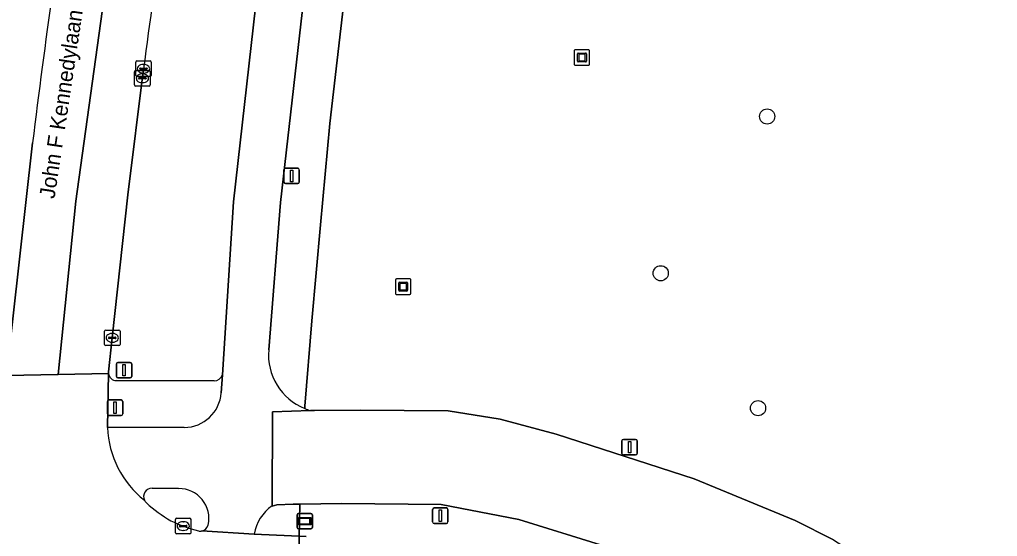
# Model space of a CAD drawing. Extents: x 161477 to 163040, y 383680 to 384871.
# Drawn here: x 161513.6 to 161576.6, y 384158.1 to 384191.4 of the extents above; entities that cross this region are included whole.
import ezdxf

# ---------------------------------------------------------------- set-up
doc = ezdxf.new("R2010")
doc.units = 0
for name, color, linetype in [('IMGEO_Afsluitpaal', 7, 'Continuous'), ('IMGEO_Berm_groen', 7, 'Continuous'), ('IMGEO_Boom', 7, 'Continuous'), ('IMGEO_Fietspad_gesloten', 7, 'Continuous'), ('IMGEO_Groenvoorziening', 7, 'Continuous'), ('IMGEO_Informatiebord', 7, 'Continuous'), ('IMGEO_Kolk', 7, 'Continuous'), ('IMGEO_Kunstobject', 7, 'Continuous'), ('IMGEO_Lichtmast', 7, 'Continuous'), ('IMGEO_Openbare_ruimte_label', 7, 'Continuous'), ('IMGEO_Rijbaan_lokaal_gesloten', 7, 'Continuous'), ('IMGEO_Verkeerseiland_open', 7, 'Continuous'), ('IMGEO_Voetpad_open', 7, 'Continuous')]:
    doc.layers.add(name, color=color, linetype=linetype)

msp = doc.modelspace()

# ---------------------------------------------------------------- linework, layer by layer
at = {"layer": 'IMGEO_Afsluitpaal'}
for p, q in [((161540.238, 384159.033), (161540.238, 384159.833)), ((161540.238, 384159.833), (161540.238, 384159.033)), ((161540.338, 384159.933), (161541.128, 384159.933)), ((161541.128, 384159.933), (161540.338, 384159.933)), ((161541.228, 384159.833), (161541.228, 384159.033)), ((161541.228, 384159.033), (161541.228, 384159.833)), ((161541.128, 384158.933), (161540.338, 384158.933)), ((161540.338, 384158.933), (161541.128, 384158.933))]:
    msp.add_line(p, q, dxfattribs=at)
msp.add_lwpolyline([(161540.658, 384159.808), (161540.808, 384159.808), (161540.808, 384159.058), (161540.658, 384159.058), (161540.658, 384159.808)], dxfattribs=at)
for centre, start, end in [((161540.338, 384159.833), 90, 180), ((161540.338, 384159.833), 90, 180), ((161541.128, 384159.833), 0, 90), ((161541.128, 384159.833), 360, 90), ((161540.338, 384159.033), 180, 270), ((161540.338, 384159.033), 180, 270), ((161541.128, 384159.033), 270, 0), ((161541.128, 384159.033), 270, 0)]:
    msp.add_arc(centre, 0.1, start, end, dxfattribs=at)
at = {"layer": 'IMGEO_Berm_groen'}
for points in [[(161526.694, 384168.506), (161527.414, 384179.645), (161529.975, 384202.277)], [(161521.614, 384188.219), (161520.593, 384180.095), (161519.6, 384170.889), (161519.361, 384168.707), (161519.359, 384168.599)], [(161512.791, 384168.464), (161514.46, 384183.443)], [(161519.865, 384168.138), (161526.157, 384168.123)]]:
    msp.add_lwpolyline(points, dxfattribs=at)
for centre, radius, start, end in [((162057.477, 384117.846), 540.464, 170.55863, 172.51839), ((162109.656, 384109.826), 599.731, 171.073784, 172.949186), ((161519.863, 384168.644), 0.506, 185.09075, 270.23801), ((161526.166, 384168.679), 0.556, 269.09368, 341.90089)]:
    msp.add_arc(centre, radius, start, end, dxfattribs=at)
at = {"layer": 'IMGEO_Boom'}
for centre in [(161561.799, 384185.146), (161554.939, 384175.046), (161561.211, 384166.361)]:
    msp.add_circle(centre, 0.489, dxfattribs=at)
at = {"layer": 'IMGEO_Fietspad_gesloten'}
for points in [[(161529.975, 384202.277), (161527.414, 384179.645), (161526.694, 384168.506), (161526.619, 384167.347)], [(161529.68, 384170.126), (161530.438, 384179.604), (161532.983, 384201.847)], [(161529.9, 384160.057), (161529.932, 384166.127), (161532.366, 384166.206)], [(161524.242, 384165.121), (161519.295, 384165.127), (161519.295, 384165.103)], [(161522.165, 384161.2), (161523.875, 384161.181)], [(161525.377, 384158.45), (161528.739, 384158.251)]]:
    msp.add_lwpolyline(points, dxfattribs=at)
for centre, radius, start, end in [((161533.407, 384169.799), 3.741, 174.98399, 247.87637), ((161524.238, 384167.508), 2.387, 270.10106, 356.14115), ((161533.441, 384169.917), 3.864, 248.07224, 253.84776), ((161525.509, 384165.325), 6.218, 182.04547, 231.84798), ((161522.156, 384160.662), 0.538, 89.05097, 204.92763), ((161523.9, 384159.256), 1.925, 347.31957, 90.75225), ((161531.403, 384157.815), 2.7, 123.83283, 170.69672), ((161525.26, 384158.974), 0.537, 282.62431, 344.89447)]:
    msp.add_arc(centre, radius, start, end, dxfattribs=at)
at = {"layer": 'IMGEO_Groenvoorziening'}
for points in [[(161535.276, 384198.984), (161533.61, 384184.698), (161533.007, 384178.166), (161532.455, 384171.988), (161532.008, 384166.49), (161531.998, 384166.333)], [(161532.366, 384166.206), (161532.624, 384166.214), (161535.575, 384166.233), (161541.235, 384166.197), (161544.598, 384165.657), (161548.197, 384164.682), (161557.091, 384161.811), (161563.61, 384159.132), (161566.076, 384157.88), (161569.496, 384155.698), (161578.833, 384149.227), (161587.525, 384143.756), (161590.641, 384142.225), (161593.952, 384140.949), (161597.484, 384140.032), (161602.329, 384139.159), (161605.427, 384138.863), (161609.285, 384138.775), (161612.928, 384139.04), (161616.16, 384139.58), (161620.746, 384140.706), (161623.5, 384141.579), (161626.462, 384142.748)], [(161628.281, 384137.114), (161624.648, 384135.722), (161619.424, 384134.087), (161616.059, 384133.366), (161612.429, 384132.961), (161606.375, 384132.939), (161598.545, 384133.672), (161592.268, 384135.114), (161586.623, 384137.484), (161581.539, 384140.473), (161576.425, 384143.894), (161572.308, 384147.016), (161565.467, 384151.61), (161561.106, 384153.825), (161556.746, 384155.662), (161551.068, 384157.566), (161545.8, 384159.194), (161540.797, 384160.153), (161534.39, 384160.217), (161531.691, 384160.176), (161531.642, 384158.109), (161532.1, 384158.086)]]:
    msp.add_lwpolyline(points, dxfattribs=at)
msp.add_arc((161533.441, 384169.917), 3.864, 248.07224, 253.84776, dxfattribs=at)
at = {"layer": 'IMGEO_Informatiebord'}
for p, q in [((161531.505, 384158.68), (161531.505, 384159.48)), ((161531.505, 384159.48), (161531.505, 384158.68)), ((161531.605, 384159.58), (161532.395, 384159.58)), ((161532.395, 384159.58), (161531.605, 384159.58)), ((161532.495, 384159.48), (161532.495, 384158.68)), ((161532.495, 384158.68), (161532.495, 384159.48)), ((161532.395, 384158.58), (161531.605, 384158.58)), ((161531.605, 384158.58), (161532.395, 384158.58))]:
    msp.add_line(p, q, dxfattribs=at)
for points in [[(161531.606, 384159.312), (161532.394, 384159.312), (161532.394, 384158.848), (161531.606, 384158.848), (161531.606, 384159.312)], [(161531.671, 384159.247), (161531.671, 384158.913), (161532.329, 384158.913), (161532.329, 384159.247), (161531.671, 384159.247)]]:
    msp.add_lwpolyline(points, dxfattribs=at)
for centre, start, end in [((161531.605, 384159.48), 90, 180), ((161531.605, 384159.48), 90, 180), ((161532.395, 384159.48), 0, 90), ((161532.395, 384159.48), 360, 90), ((161531.605, 384158.68), 180, 270), ((161531.605, 384158.68), 180, 270), ((161532.395, 384158.68), 270, 0), ((161532.395, 384158.68), 270, 0)]:
    msp.add_arc(centre, 0.1, start, end, dxfattribs=at)
at = {"layer": 'IMGEO_Kolk'}
for p, q in [((161521.113, 384187.793), (161521.113, 384188.645)), ((161521.188, 384188.719), (161522.04, 384188.719)), ((161521.601, 384188.499), (161521.626, 384188.499)), ((161522.114, 384188.645), (161522.114, 384187.793)), ((161521.04, 384187.177), (161521.04, 384188.029)), ((161521.115, 384188.103), (161521.967, 384188.103)), ((161521.372, 384188.213), (161521.372, 384188.225)), ((161521.81, 384188.176), (161521.412, 384188.176)), ((161521.415, 384188.262), (161521.813, 384188.262)), ((161521.528, 384187.883), (161521.553, 384187.883)), ((161521.624, 384187.939), (161521.599, 384187.939)), ((161521.856, 384188.225), (161521.856, 384188.213)), ((161522.041, 384188.029), (161522.041, 384187.177)), ((161521.967, 384187.103), (161521.115, 384187.103)), ((161522.04, 384187.719), (161521.188, 384187.719)), ((161521.299, 384187.597), (161521.299, 384187.609)), ((161521.737, 384187.56), (161521.339, 384187.56)), ((161521.342, 384187.646), (161521.74, 384187.646)), ((161521.551, 384187.323), (161521.526, 384187.323)), ((161521.783, 384187.609), (161521.783, 384187.597)), ((161519.174, 384171.389), (161520.026, 384171.389)), ((161519.099, 384170.463), (161519.099, 384171.315)), ((161519.358, 384170.883), (161519.358, 384170.895)), ((161519.796, 384170.846), (161519.398, 384170.846)), ((161519.401, 384170.932), (161519.799, 384170.932)), ((161519.587, 384171.169), (161519.612, 384171.169)), ((161519.842, 384170.895), (161519.842, 384170.883)), ((161520.1, 384171.315), (161520.1, 384170.463)), ((161520.026, 384170.389), (161519.174, 384170.389)), ((161519.61, 384170.609), (161519.585, 384170.609)), ((161523.671, 384158.34), (161523.671, 384159.192)), ((161523.746, 384159.266), (161524.598, 384159.266)), ((161523.93, 384158.76), (161523.93, 384158.772)), ((161523.973, 384158.809), (161524.371, 384158.809)), ((161524.159, 384159.046), (161524.184, 384159.046)), ((161524.414, 384158.772), (161524.414, 384158.76)), ((161524.672, 384159.192), (161524.672, 384158.34)), ((161524.598, 384158.266), (161523.746, 384158.266)), ((161524.368, 384158.723), (161523.97, 384158.723)), ((161524.182, 384158.486), (161524.157, 384158.486))]:
    msp.add_line(p, q, dxfattribs=at)
for points in [[(161521.113, 384187.793), (161521.113, 384188.645)], [(161521.188, 384188.719), (161522.04, 384188.719)], [(161522.114, 384188.645), (161522.114, 384187.793)], [(161521.04, 384187.177), (161521.04, 384188.029)], [(161521.115, 384188.103), (161521.967, 384188.103)], [(161522.041, 384188.029), (161522.041, 384187.177)], [(161521.967, 384187.103), (161521.115, 384187.103)], [(161522.04, 384187.719), (161521.188, 384187.719)], [(161519.174, 384171.389), (161520.026, 384171.389)], [(161519.099, 384170.463), (161519.099, 384171.315)], [(161520.1, 384171.315), (161520.1, 384170.463)], [(161520.026, 384170.389), (161519.174, 384170.389)], [(161523.671, 384158.34), (161523.671, 384159.192)], [(161523.746, 384159.266), (161524.598, 384159.266)], [(161524.672, 384159.192), (161524.672, 384158.34)], [(161524.598, 384158.266), (161523.746, 384158.266)]]:
    msp.add_lwpolyline(points, dxfattribs=at)
for centre, radius, start, end in [((161521.19, 384188.643), 0.0765, 91.55205, 178.44795), ((161521.19, 384188.643), 0.0765, 91.55205, 178.44795), ((161522.038, 384188.643), 0.0765, 1.55205, 88.44795), ((161522.038, 384188.643), 0.0765, 1.55205, 88.44795), ((161521.117, 384188.027), 0.0765, 91.55205, 178.44795), ((161521.117, 384188.027), 0.0765, 91.55205, 178.44795), ((161521.19, 384187.795), 0.0765, 181.55205, 268.44795), ((161521.19, 384187.795), 0.0765, 181.55205, 268.44795), ((161521.412, 384188.222), 0.0403, 85.87752, 175.75265), ((161521.409, 384188.212), 0.0366, 178.93798, 274.71019), ((161521.813, 384188.219), 0.043, 264.86636, 352.45326), ((161521.817, 384188.224), 0.0386, 1.73085, 96.63898), ((161521.965, 384188.027), 0.0765, 1.55205, 88.44795), ((161521.965, 384188.027), 0.0765, 1.55205, 88.44795), ((161522.038, 384187.795), 0.0765, 271.55205, 358.44795), ((161522.038, 384187.795), 0.0765, 271.55205, 358.44795), ((161521.117, 384187.179), 0.0765, 181.55205, 268.44795), ((161521.117, 384187.179), 0.0765, 181.55205, 268.44795), ((161521.339, 384187.606), 0.0403, 85.87752, 175.75265), ((161521.336, 384187.596), 0.0366, 178.93798, 274.71019), ((161521.74, 384187.603), 0.043, 264.86636, 352.45326), ((161521.744, 384187.608), 0.0386, 1.73085, 96.63898), ((161521.965, 384187.179), 0.0765, 271.55205, 358.44795), ((161521.965, 384187.179), 0.0765, 271.55205, 358.44795), ((161519.176, 384171.313), 0.0765, 91.55205, 178.44795), ((161519.176, 384171.313), 0.0765, 91.55205, 178.44795), ((161520.024, 384171.313), 0.0765, 1.55205, 88.44795), ((161520.024, 384171.313), 0.0765, 1.55205, 88.44795), ((161519.398, 384170.892), 0.0403, 85.87752, 175.75265), ((161519.395, 384170.882), 0.0366, 178.93798, 274.71019), ((161519.799, 384170.889), 0.043, 264.86636, 352.45326), ((161519.803, 384170.894), 0.0386, 1.73085, 96.63898), ((161519.176, 384170.465), 0.0765, 181.55205, 268.44795), ((161519.176, 384170.465), 0.0765, 181.55205, 268.44795), ((161520.024, 384170.465), 0.0765, 271.55205, 358.44795), ((161520.024, 384170.465), 0.0765, 271.55205, 358.44795), ((161523.748, 384159.19), 0.0765, 91.55205, 178.44795), ((161523.748, 384159.19), 0.0765, 91.55205, 178.44795), ((161523.97, 384158.769), 0.0403, 85.87752, 175.75265), ((161523.967, 384158.759), 0.0366, 178.93798, 274.71019), ((161524.371, 384158.766), 0.043, 264.86636, 352.45326), ((161524.375, 384158.771), 0.0386, 1.73085, 96.63898), ((161524.596, 384159.19), 0.0765, 1.55205, 88.44795), ((161524.596, 384159.19), 0.0765, 1.55205, 88.44795), ((161523.748, 384158.342), 0.0765, 181.55205, 268.44795), ((161523.748, 384158.342), 0.0765, 181.55205, 268.44795), ((161524.596, 384158.342), 0.0765, 271.55205, 358.44795), ((161524.596, 384158.342), 0.0765, 271.55205, 358.44795)]:
    msp.add_arc(centre, radius, start, end, dxfattribs=at)
for centre, major_axis, ratio, start_param, end_param in [((161521.6, 384188.219), (-0.387, 0.002), 0.722429, 4.712389, 7.853982), ((161521.625, 384188.219), (-0.39, 0.002), 0.717154, 1.570796, 4.712389), ((161521.527, 384187.603), (-0.387, 0.002), 0.722429, 4.712389, 7.853982), ((161521.552, 384187.603), (-0.39, 0.002), 0.717154, 1.570796, 4.712389), ((161519.586, 384170.889), (-0.387, 0.002), 0.722429, 4.712389, 7.853982), ((161519.611, 384170.889), (-0.39, 0.002), 0.717154, 1.570796, 4.712389), ((161524.158, 384158.766), (-0.387, 0.002), 0.722429, 4.712389, 7.853982), ((161524.183, 384158.766), (-0.39, 0.002), 0.717154, 1.570796, 4.712389)]:
    msp.add_ellipse(centre, major_axis=major_axis, ratio=ratio, start_param=start_param, end_param=end_param, dxfattribs=at)
at = {"layer": 'IMGEO_Kunstobject'}
for p, q in [((161549.36, 384189.359), (161549.36, 384188.518)), ((161549.36, 384189.359), (161549.36, 384188.518)), ((161550.276, 384189.443), (161549.435, 384189.443)), ((161550.276, 384189.443), (161549.435, 384189.443)), ((161549.574, 384188.707), (161549.574, 384189.181)), ((161549.624, 384189.231), (161550.098, 384189.231)), ((161549.654, 384189.131), (161549.654, 384188.757)), ((161550.048, 384189.151), (161549.674, 384189.151)), ((161550.068, 384188.757), (161550.068, 384189.131)), ((161550.148, 384189.181), (161550.148, 384188.707)), ((161550.36, 384188.527), (161550.36, 384189.368)), ((161550.36, 384188.527), (161550.36, 384189.368)), ((161549.444, 384188.443), (161550.285, 384188.443)), ((161549.444, 384188.443), (161550.285, 384188.443)), ((161550.098, 384188.657), (161549.624, 384188.657)), ((161549.674, 384188.737), (161550.048, 384188.737)), ((161537.841, 384174.601), (161537.841, 384173.76)), ((161537.841, 384174.601), (161537.841, 384173.76)), ((161538.757, 384174.685), (161537.916, 384174.685)), ((161538.757, 384174.685), (161537.916, 384174.685)), ((161538.841, 384173.769), (161538.841, 384174.61)), ((161538.841, 384173.769), (161538.841, 384174.61)), ((161538.055, 384173.949), (161538.055, 384174.423)), ((161538.105, 384174.473), (161538.579, 384174.473)), ((161538.579, 384173.899), (161538.105, 384173.899)), ((161538.135, 384174.373), (161538.135, 384173.999)), ((161538.529, 384174.393), (161538.155, 384174.393)), ((161538.155, 384173.979), (161538.529, 384173.979)), ((161538.549, 384173.999), (161538.549, 384174.373)), ((161538.629, 384174.423), (161538.629, 384173.949)), ((161537.925, 384173.685), (161538.766, 384173.685)), ((161537.925, 384173.685), (161538.766, 384173.685))]:
    msp.add_line(p, q, dxfattribs=at)
for centre, radius, start, end in [((161549.438, 384189.365), 0.0779, 92.4484, 184.28452), ((161549.438, 384189.365), 0.0779, 92.4484, 184.28452), ((161549.624, 384189.181), 0.05, 90, 180), ((161549.674, 384189.131), 0.02, 90, 180), ((161550.048, 384189.131), 0.02, 360, 90), ((161550.098, 384189.181), 0.05, 360, 90), ((161550.282, 384189.365), 0.0779, 2.4484, 94.28452), ((161550.282, 384189.365), 0.0779, 2.4484, 94.28452), ((161549.438, 384188.521), 0.0779, 182.4484, 274.28452), ((161549.438, 384188.521), 0.0779, 182.4484, 274.28452), ((161549.624, 384188.707), 0.05, 180, 270), ((161549.674, 384188.757), 0.02, 180, 270), ((161550.048, 384188.757), 0.02, 270, 0), ((161550.098, 384188.707), 0.05, 270, 0), ((161550.282, 384188.521), 0.0779, 272.4484, 4.28452), ((161550.282, 384188.521), 0.0779, 272.4484, 4.28452), ((161537.919, 384174.607), 0.0779, 92.4484, 184.28452), ((161537.919, 384174.607), 0.0779, 92.4484, 184.28452), ((161538.763, 384174.607), 0.0779, 2.4484, 94.28452), ((161538.763, 384174.607), 0.0779, 2.4484, 94.28452), ((161538.105, 384174.423), 0.05, 90, 180), ((161538.105, 384173.949), 0.05, 180, 270), ((161538.155, 384174.373), 0.02, 90, 180), ((161538.155, 384173.999), 0.02, 180, 270), ((161538.529, 384174.373), 0.02, 360, 90), ((161538.529, 384173.999), 0.02, 270, 0), ((161538.579, 384174.423), 0.05, 360, 90), ((161538.579, 384173.949), 0.05, 270, 0), ((161537.919, 384173.763), 0.0779, 182.4484, 274.28452), ((161537.919, 384173.763), 0.0779, 182.4484, 274.28452), ((161538.763, 384173.763), 0.0779, 272.4484, 4.28452), ((161538.763, 384173.763), 0.0779, 272.4484, 4.28452)]:
    msp.add_arc(centre, radius, start, end, dxfattribs=at)
at = {"layer": 'IMGEO_Lichtmast'}
for p, q in [((161530.659, 384180.919), (161530.659, 384181.719)), ((161530.659, 384181.719), (161530.659, 384180.919)), ((161530.759, 384181.819), (161531.549, 384181.819)), ((161531.549, 384181.819), (161530.759, 384181.819)), ((161531.649, 384181.719), (161531.649, 384180.919)), ((161531.649, 384180.919), (161531.649, 384181.719)), ((161531.549, 384180.819), (161530.759, 384180.819)), ((161530.759, 384180.819), (161531.549, 384180.819)), ((161519.862, 384168.406), (161519.862, 384169.206)), ((161519.862, 384169.206), (161519.862, 384168.406)), ((161519.962, 384169.306), (161520.752, 384169.306)), ((161520.752, 384169.306), (161519.962, 384169.306)), ((161520.852, 384169.206), (161520.852, 384168.406)), ((161520.852, 384168.406), (161520.852, 384169.206)), ((161520.752, 384168.306), (161519.962, 384168.306)), ((161519.962, 384168.306), (161520.752, 384168.306)), ((161519.285, 384165.988), (161519.285, 384166.788)), ((161519.285, 384166.788), (161519.285, 384165.988)), ((161519.385, 384166.888), (161520.175, 384166.888)), ((161520.175, 384166.888), (161519.385, 384166.888)), ((161520.275, 384166.788), (161520.275, 384165.988)), ((161520.275, 384165.988), (161520.275, 384166.788)), ((161520.175, 384165.888), (161519.385, 384165.888)), ((161519.385, 384165.888), (161520.175, 384165.888)), ((161552.434, 384163.447), (161552.434, 384164.247)), ((161552.434, 384164.247), (161552.434, 384163.447)), ((161552.534, 384164.347), (161553.324, 384164.347)), ((161553.324, 384164.347), (161552.534, 384164.347)), ((161553.424, 384164.247), (161553.424, 384163.447)), ((161553.424, 384163.447), (161553.424, 384164.247)), ((161553.324, 384163.347), (161552.534, 384163.347)), ((161552.534, 384163.347), (161553.324, 384163.347))]:
    msp.add_line(p, q, dxfattribs=at)
for points in [[(161531.079, 384181.694), (161531.229, 384181.694), (161531.229, 384180.944), (161531.079, 384180.944), (161531.079, 384181.694)], [(161520.282, 384169.181), (161520.432, 384169.181), (161520.432, 384168.431), (161520.282, 384168.431), (161520.282, 384169.181)], [(161519.705, 384166.763), (161519.855, 384166.763), (161519.855, 384166.013), (161519.705, 384166.013), (161519.705, 384166.763)], [(161552.854, 384164.222), (161553.004, 384164.222), (161553.004, 384163.472), (161552.854, 384163.472), (161552.854, 384164.222)]]:
    msp.add_lwpolyline(points, dxfattribs=at)
for centre, start, end in [((161530.759, 384181.719), 90, 180), ((161530.759, 384181.719), 90, 180), ((161531.549, 384181.719), 0, 90), ((161531.549, 384181.719), 360, 90), ((161530.759, 384180.919), 180, 270), ((161530.759, 384180.919), 180, 270), ((161531.549, 384180.919), 270, 0), ((161531.549, 384180.919), 270, 0), ((161519.962, 384169.206), 90, 180), ((161519.962, 384169.206), 90, 180), ((161520.752, 384169.206), 0, 90), ((161520.752, 384169.206), 360, 90), ((161519.962, 384168.406), 180, 270), ((161519.962, 384168.406), 180, 270), ((161520.752, 384168.406), 270, 0), ((161520.752, 384168.406), 270, 0), ((161519.385, 384166.788), 90, 180), ((161519.385, 384166.788), 90, 180), ((161520.175, 384166.788), 0, 90), ((161520.175, 384166.788), 360, 90), ((161519.385, 384165.988), 180, 270), ((161519.385, 384165.988), 180, 270), ((161520.175, 384165.988), 270, 0), ((161520.175, 384165.988), 270, 0), ((161552.534, 384164.247), 90, 180), ((161552.534, 384164.247), 90, 180), ((161553.324, 384164.247), 0, 90), ((161553.324, 384164.247), 360, 90), ((161552.534, 384163.447), 180, 270), ((161552.534, 384163.447), 180, 270), ((161553.324, 384163.447), 270, 0), ((161553.324, 384163.447), 270, 0)]:
    msp.add_arc(centre, 0.1, start, end, dxfattribs=at)
at = {"layer": 'IMGEO_Rijbaan_lokaal_gesloten'}
for points in [[(161514.46, 384183.443), (161512.791, 384168.464), (161516.107, 384168.532), (161517.261, 384179.696), (161519.595, 384196.57), (161523.029, 384218.462), (161527.965, 384241.641), (161533.76, 384265.249), (161540.413, 384288.105), (161546.744, 384307.421), (161553.29, 384325.984), (161561.445, 384344.977), (161571.317, 384366.867), (161581.619, 384388.221), (161592.563, 384409.681), (161601.577, 384427.493), (161617.886, 384459.039), (161630.548, 384484.682), (161648.789, 384520.091), (161657.802, 384538.01), (161663.424, 384548.94)], [(161519.595, 384196.57), (161517.261, 384179.696), (161516.107, 384168.532), (161519.359, 384168.599), (161519.361, 384168.707), (161519.6, 384170.889), (161520.593, 384180.095), (161521.614, 384188.219)], [(161519.295, 384165.103), (161519.295, 384165.127), (161519.359, 384168.599), (161516.107, 384168.532), (161512.791, 384168.464), (161512.421, 384165.07), (161511.934, 384160.599), (161511.923, 384160.495)], [(161566.076, 384157.88), (161563.61, 384159.132), (161557.091, 384161.811), (161548.197, 384164.682), (161544.598, 384165.657), (161541.235, 384166.197), (161535.575, 384166.233), (161532.624, 384166.214), (161532.366, 384166.206), (161529.932, 384166.127), (161529.9, 384160.057), (161530.199, 384160.129), (161531.252, 384160.169), (161531.691, 384160.176), (161534.39, 384160.217), (161540.797, 384160.153), (161545.8, 384159.194), (161551.068, 384157.566)], [(161524.815, 384149.17), (161528.268, 384149.264), (161531.725, 384149.358), (161531.642, 384158.109), (161531.156, 384158.133), (161528.739, 384158.251), (161525.377, 384158.45)], [(161532.1, 384158.086), (161531.642, 384158.109), (161531.725, 384149.358), (161531.759, 384149.36), (161531.793, 384149.36), (161532.03, 384149.353), (161533.25, 384149.288)]]:
    msp.add_lwpolyline(points, dxfattribs=at)
for centre, radius, start, end in [((162057.477, 384117.846), 540.464, 170.55863, 172.51839), ((162109.656, 384109.826), 599.731, 171.073784, 172.949186), ((161525.509, 384165.325), 6.218, 182.04547, 231.84798), ((161522.165, 384160.67), 0.55, 205.28648, 228.65905), ((161528.145, 384167.274), 9.459, 227.88801, 239.70241), ((161527.914, 384168.639), 10.559, 244.5303, 254.80449), ((161525.262, 384159), 0.562, 258.13673, 281.86327)]:
    msp.add_arc(centre, radius, start, end, dxfattribs=at)
at = {"layer": 'IMGEO_Verkeerseiland_open'}
for points in [[(161523.875, 384161.181), (161522.165, 384161.2)], [(161528.739, 384158.251), (161531.156, 384158.133), (161531.642, 384158.109), (161531.691, 384160.176)], [(161531.691, 384160.176), (161531.252, 384160.169), (161530.199, 384160.129), (161529.9, 384160.057)]]:
    msp.add_lwpolyline(points, dxfattribs=at)
for centre, radius, start, end in [((161522.156, 384160.662), 0.538, 89.05097, 204.92763), ((161523.9, 384159.256), 1.925, 347.31957, 90.75225), ((161522.165, 384160.67), 0.55, 205.28648, 228.65905), ((161528.145, 384167.274), 9.459, 227.88801, 239.70241), ((161531.403, 384157.815), 2.7, 123.83283, 170.69672), ((161527.914, 384168.639), 10.559, 244.5303, 254.80449), ((161525.26, 384158.974), 0.537, 282.62431, 344.89447), ((161525.262, 384159), 0.562, 258.13673, 281.86327)]:
    msp.add_arc(centre, radius, start, end, dxfattribs=at)
at = {"layer": 'IMGEO_Voetpad_open'}
for points in [[(161532.983, 384201.847), (161530.438, 384179.604), (161529.68, 384170.126)], [(161531.998, 384166.333), (161532.008, 384166.49), (161532.455, 384171.988), (161533.007, 384178.166), (161533.61, 384184.698), (161535.276, 384198.984)], [(161519.359, 384168.599), (161519.295, 384165.127), (161524.242, 384165.121)], [(161526.619, 384167.347), (161526.694, 384168.506)], [(161526.157, 384168.123), (161519.865, 384168.138)]]:
    msp.add_lwpolyline(points, dxfattribs=at)
for centre, radius, start, end in [((161533.407, 384169.799), 3.741, 174.98399, 247.87637), ((161519.863, 384168.644), 0.506, 185.09075, 270.23801), ((161526.166, 384168.679), 0.556, 269.09368, 341.90089), ((161524.238, 384167.508), 2.387, 270.10106, 356.14115)]:
    msp.add_arc(centre, radius, start, end, dxfattribs=at)

# ---------------------------------------------------------------- texts
at = {"layer": 'IMGEO_Openbare_ruimte_label'}
msp.add_text('John F Kennedylaan', height=1, rotation=81.43241, dxfattribs=at).set_placement((161515.877, 384179.812))

doc.saveas('drawing.dxf')
